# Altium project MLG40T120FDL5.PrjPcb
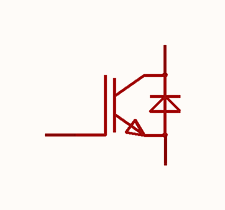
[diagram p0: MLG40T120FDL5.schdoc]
1 sheet, 1 parts. Net scope: global (net labels, ports and power ports of the same name join across sheets).

## Sheet MLG40T120FDL5.schdoc
size 127 x 101 mm

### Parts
Q?  mlg40t120fdl5  [TO-247-3_L15.6-W4.7-P5.45-L]  (value not drawn)

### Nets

Not connected (* = marked no-connect by the designer): Q? 1(G) 2(C) 3(E)

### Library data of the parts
Q? = mlg40t120fdl5: IGBT类型:FS(场截止);耗散功率(Pd):428W;集射极击穿电压(Vces):1.2kV;集电极电流(Ic):80A;; Manufacturer: minos(迈诺斯); AddInBom: yes; ModelId: c7ff900f52804e23982f5352ae914652; ModelTransform: 614.9594,185.078,0,0,0,0,0,14.252,-196.85; Pd - Power Dissipation: 428W; Collector-Emitter Breakdown Voltage (Vces): 1.2kV; Current - Collector(Ic): 80A; Current - Collector Pulsed (Icm): 160A; Collector Cut-Off Current (Ices): 35uA; Vce Saturation(VCE(sat)): 1.65V; Gate-Emitter Threshold Voltage (Vge(th)@Ic): 5.5V; Gate Charge(Qg): 108nC@15V; Input Capacitance(Cies): 2.048nF; Output Capacitance(Coes): 89pF; Reverse Transfer Capacitance (Cres): 13pF; Td(on): 17ns；16ns; Td(off): 165ns；137ns; Turn-On Energy (Eon): 3.3mJ；2.65mJ; Switching Energy(Eoff): 3.7mJ；2.8mJ; Reverse Recovery Time(trr): 610ns；460ns；237ns；323ns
